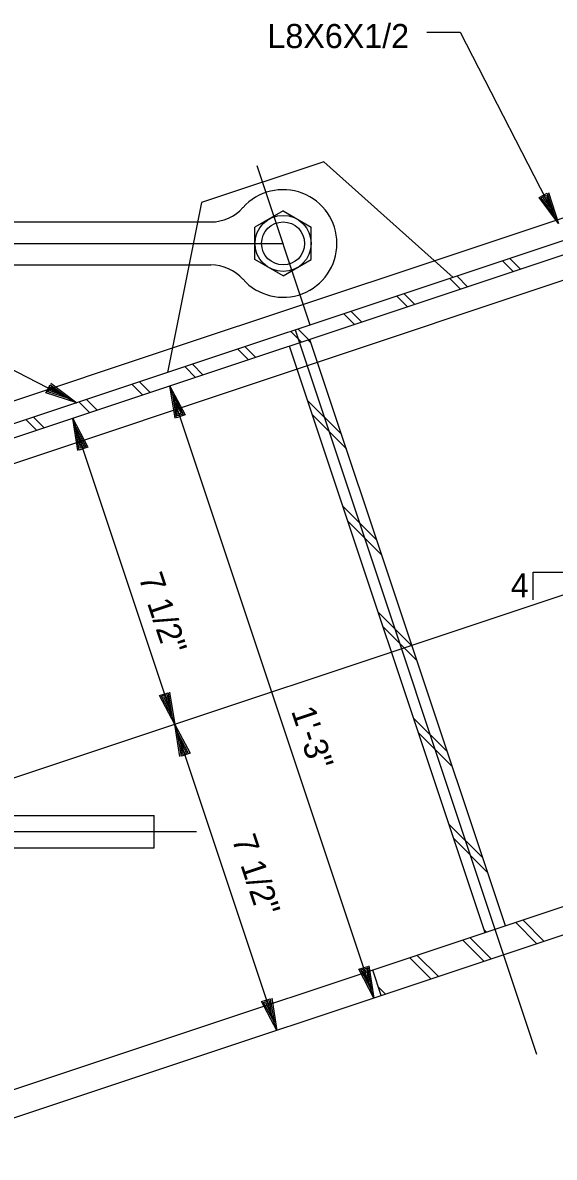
# Model space of a CAD drawing. Extents: x 0.1 to 13.5, y 0.1 to 9.5.
# Drawn here: x 3.942 to 4.972, y 5.175 to 7.373 of the extents above; entities that cross this region are included whole.
import ezdxf

# ---------------------------------------------------------------- set-up
doc = ezdxf.new("R2010")
doc.units = 0
for name, color, linetype in [('Level 1', 7, 'Continuous'), ('Level 13', 7, 'Continuous'), ('Level 25', 7, 'Continuous'), ('Level 3', 7, 'Continuous'), ('Level 44', 7, 'Continuous'), ('Level 50', 7, 'Continuous')]:
    doc.layers.add(name, color=color, linetype=linetype)

msp = doc.modelspace()

# ---------------------------------------------------------------- linework, layer by layer
at = {"layer": 'Level 13'}
for p, q in [((4.4465, 7.008), (4.3919, 6.9765)), ((4.4465, 7.008), (4.501, 6.9765)), ((4.3919, 6.9138), (4.3919, 6.9765)), ((4.501, 6.9138), (4.501, 6.9765)), ((4.4465, 6.8823), (4.3919, 6.9138)), ((4.4465, 6.8823), (4.501, 6.9138))]:
    msp.add_line(p, q, dxfattribs=at)
msp.add_circle((4.4466, 6.9451), 0.0544, dxfattribs=at)
at = {"layer": 'Level 25'}
for p, q in [((4.5256, 7.1033), (4.2885, 7.0242)), ((4.5256, 7.1033), (4.776, 6.8793)), ((4.4993, 6.787), (4.3966, 7.0952)), ((4.2885, 7.0242), (4.2226, 6.6948)), ((5.0896, 7.0277), (4.7402, 6.9113)), ((3.4993, 6.9868), (4.3068, 6.9868)), ((5.1028, 6.9882), (3.6347, 6.4989)), ((5.111, 6.9635), (3.6139, 6.4644)), ((1.8228, 6.9451), (4.4466, 6.9451)), ((3.4993, 6.9035), (4.3068, 6.9035)), ((5.1258, 6.919), (3.6972, 6.4428)), ((4.7402, 6.9113), (4.232, 6.7419)), ((4.9381, 5.3741), (4.4703, 6.7774)), ((4.8771, 5.6228), (4.4983, 6.7593)), ((4.232, 6.7419), (3.7389, 6.5775)), ((3.8535, 6.7364), (4.0474, 6.6364)), ((4.8376, 5.6096), (4.4588, 6.7461)), ((4.6226, 5.4831), (4.2274, 6.6689)), ((4.2368, 6.0133), (4.0392, 6.6062)), ((5.3086, 6.3706), (3.6139, 5.8056)), ((4.9312, 6.2544), (4.9312, 6.3083)), ((4.9312, 6.3083), (5.0816, 6.3083)), ((4.4345, 5.4204), (4.2368, 6.0133)), ((3.6972, 5.8369), (4.1972, 5.8369)), ((5.4898, 5.827), (3.6972, 5.2295)), ((4.1972, 5.7744), (4.1972, 5.8369)), ((3.0381, 5.8056), (4.2789, 5.8056)), ((5.5063, 5.7776), (3.6972, 5.1746)), ((3.6972, 5.7744), (4.1972, 5.7744)), ((4.6366, 5.4878), (4.6202, 5.5372))]:
    msp.add_line(p, q, dxfattribs=at)
msp.add_circle((4.4466, 6.9451), 0.0417, dxfattribs=at)
for centre, radius, start, end in [((4.4466, 6.9451), 0.1042, 221.8103, 138.1897), ((4.3068, 7.0701), 0.0833, 270, 318.1897), ((4.3068, 6.8201), 0.0833, 41.8103, 90)]:
    msp.add_arc(centre, radius, start, end, dxfattribs=at)
at = {"layer": 'Level 3'}
for points in [[(4.7248, 7.3542), (4.7898, 7.3542), (4.9799, 6.9835)], [(4.9606, 7.0437), (4.9799, 6.9835), (4.9422, 7.0343), (4.958, 7.0423), (4.972, 6.9989), (4.9464, 7.0334), (4.9565, 7.0386), (4.9644, 7.0138), (4.9506, 7.0326), (4.9548, 7.0347), (4.9564, 7.0292)]]:
    msp.add_lwpolyline(points, dxfattribs=at)
at = {"layer": 'Level 44'}
for p, q in [((4.8924, 6.8906), (4.8718, 6.9112)), ((4.9066, 6.8953), (4.886, 6.9159)), ((4.804, 6.8612), (4.7834, 6.8818)), ((4.7899, 6.8564), (4.7693, 6.877)), ((4.6874, 6.8223), (4.6668, 6.8429)), ((4.7015, 6.827), (4.6809, 6.8476)), ((4.5848, 6.7881), (4.5642, 6.8087)), ((4.599, 6.7928), (4.5784, 6.8134)), ((4.4823, 6.7539), (4.4617, 6.7745)), ((4.4964, 6.7586), (4.4758, 6.7792)), ((4.5007, 6.752), (4.4947, 6.7581)), ((4.3798, 6.7197), (4.3592, 6.7403)), ((4.3939, 6.7244), (4.3733, 6.7451)), ((4.2772, 6.6856), (4.2566, 6.7062)), ((4.2914, 6.6903), (4.2708, 6.7109)), ((4.1747, 6.6514), (4.1541, 6.672)), ((4.1889, 6.6561), (4.1683, 6.6767)), ((4.0863, 6.6219), (4.0657, 6.6425)), ((4.5596, 6.5753), (4.4938, 6.6411)), ((4.0722, 6.6172), (4.0516, 6.6378)), ((3.9696, 6.583), (3.9491, 6.6036)), ((3.9838, 6.5878), (3.9632, 6.6083)), ((4.5691, 6.547), (4.5032, 6.6129)), ((4.628, 6.3702), (4.5621, 6.4361)), ((4.6374, 6.3419), (4.5715, 6.4078)), ((4.6964, 6.1651), (4.6305, 6.231)), ((4.7058, 6.1368), (4.6399, 6.2027)), ((4.7647, 5.9601), (4.6988, 6.026)), ((4.7741, 5.9318), (4.7083, 5.9977)), ((4.8331, 5.755), (4.7672, 5.8209)), ((4.8425, 5.7267), (4.7766, 5.7926)), ((4.9383, 5.5883), (4.8971, 5.6295)), ((4.9524, 5.593), (4.9112, 5.6342)), ((4.8407, 5.6107), (4.8355, 5.6158)), ((4.8357, 5.5541), (4.7945, 5.5953)), ((4.8499, 5.5588), (4.8087, 5.6)), ((4.7473, 5.5246), (4.7062, 5.5658)), ((4.7332, 5.5199), (4.692, 5.5611)), ((4.6448, 5.4905), (4.6312, 5.5041))]:
    msp.add_line(p, q, dxfattribs=at)
at = {"layer": 'Level 50'}
for p, q in [((4.2274, 6.6689), (4.2274, 6.6689)), ((4.0319, 6.6444), (4.0319, 6.6444)), ((4.2328, 6.6525), (4.2328, 6.6525)), ((4.0474, 6.6364), (4.0474, 6.6364)), ((4.0392, 6.6062), (4.0392, 6.6062)), ((4.0447, 6.5898), (4.0447, 6.5898)), ((4.2313, 6.0297), (4.2313, 6.0297)), ((4.2368, 6.0133), (4.2368, 6.0133)), ((4.2368, 6.0133), (4.2368, 6.0133)), ((4.2423, 5.9968), (4.2423, 5.9968)), ((4.6171, 5.4995), (4.6171, 5.4995)), ((4.6226, 5.4831), (4.6226, 5.4831)), ((4.429, 5.4368), (4.429, 5.4368)), ((4.4345, 5.4204), (4.4345, 5.4204))]:
    msp.add_line(p, q, dxfattribs=at)
for points in [[(3.9967, 6.6742), (4.0474, 6.6364), (3.9872, 6.6558), (3.9953, 6.6715), (4.0319, 6.6444), (3.9911, 6.6575), (3.9963, 6.6676), (4.0171, 6.652), (3.995, 6.6593), (3.9971, 6.6634), (4.0017, 6.6599)], [(4.2373, 6.6065), (4.2274, 6.6689), (4.2569, 6.6131), (4.2401, 6.6075), (4.2328, 6.6525), (4.2529, 6.6145), (4.2421, 6.6109), (4.2381, 6.6367), (4.2489, 6.616), (4.2444, 6.6145), (4.2436, 6.6202)], [(4.0491, 6.5438), (4.0392, 6.6062), (4.0687, 6.5503), (4.0519, 6.5448), (4.0447, 6.5898), (4.0647, 6.5518), (4.0539, 6.5482), (4.0499, 6.5739), (4.0607, 6.5533), (4.0563, 6.5518), (4.0554, 6.5575)], [(4.2269, 6.0757), (4.2368, 6.0133), (4.2073, 6.0691), (4.2241, 6.0747), (4.2313, 6.0297), (4.2113, 6.0677), (4.2221, 6.0713), (4.2261, 6.0455), (4.2153, 6.0662), (4.2198, 6.0677), (4.2206, 6.062)], [(4.2467, 5.9509), (4.2368, 6.0133), (4.2663, 5.9574), (4.2496, 5.9518), (4.2423, 5.9968), (4.2623, 5.9589), (4.2516, 5.9553), (4.2476, 5.981), (4.2583, 5.9604), (4.2539, 5.9589), (4.2531, 5.9646)], [(4.6127, 5.5455), (4.6226, 5.4831), (4.5931, 5.5389), (4.6099, 5.5445), (4.6171, 5.4995), (4.5971, 5.5375), (4.6079, 5.5411), (4.6119, 5.5153), (4.6011, 5.536), (4.6056, 5.5375), (4.6064, 5.5318)], [(4.4246, 5.4828), (4.4345, 5.4204), (4.4049, 5.4762), (4.4217, 5.4818), (4.429, 5.4368), (4.4089, 5.4748), (4.4197, 5.4783), (4.4237, 5.4526), (4.413, 5.4733), (4.4174, 5.4748), (4.4182, 5.4691)]]:
    msp.add_lwpolyline(points, dxfattribs=at)

# ---------------------------------------------------------------- texts
at = {"layer": 'Level 1'}
msp.add_text('L8X6X1/2', height=0.0467, dxfattribs=at).set_placement((4.4163, 7.3236))
at = {"layer": 'Level 25'}
for s, p in [('7 1/2"', (4.1664, 6.2983)), ('1\'-3"', (4.4618, 6.0394)), ('7 1/2"', (4.3469, 5.7911))]:
    msp.add_text(s, height=0.0467, rotation=288.4344, dxfattribs=at).set_placement(p)
msp.add_text('4', height=0.0467, dxfattribs=at).set_placement((4.8875, 6.2593))

doc.saveas('drawing.dxf')
